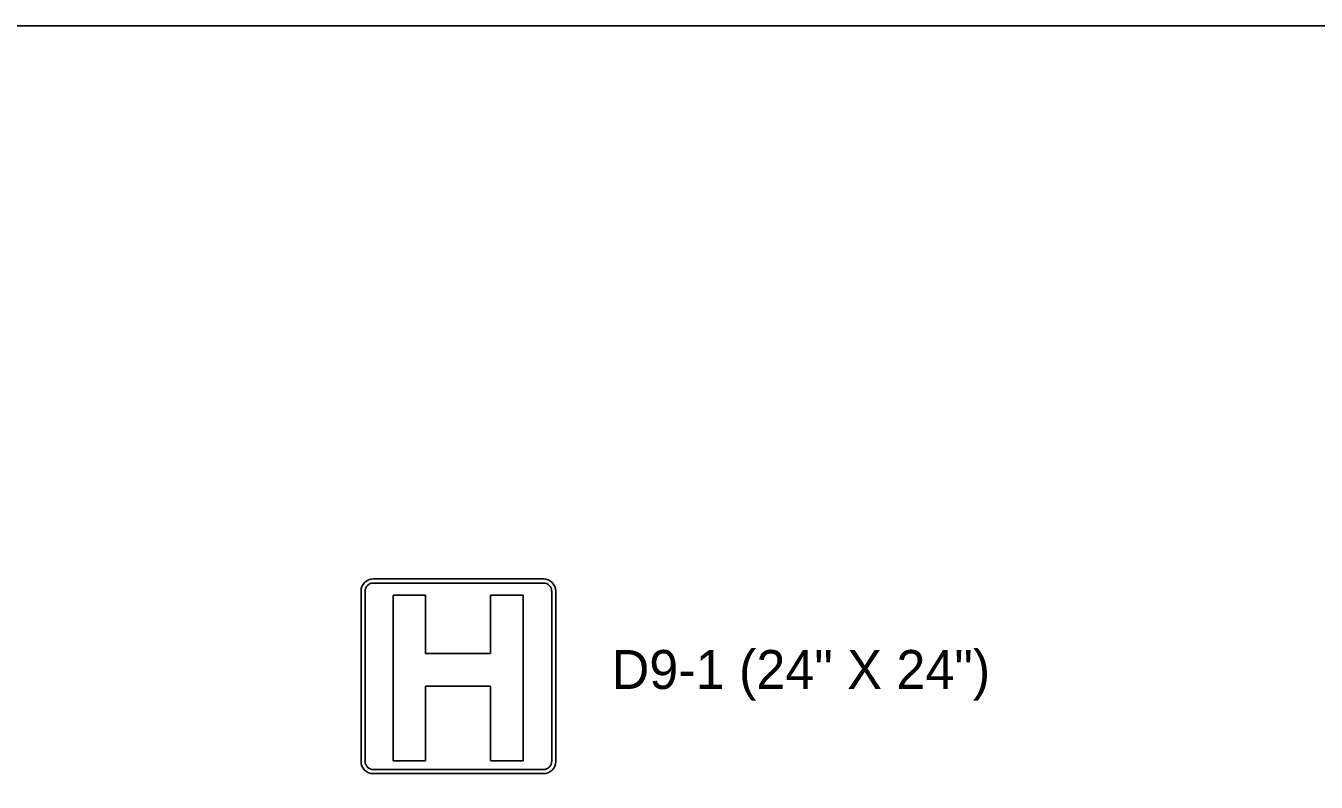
# Model space of a CAD drawing. Extents: x 1001568 to 1002149, y 1840825 to 1841423.
# Drawn here: x 1001937.13 to 1001950.38, y 1841302.89 to 1841310.67 of the extents above; entities that cross this region are included whole.
import ezdxf

# ---------------------------------------------------------------- set-up
doc = ezdxf.new("R2010")
doc.units = 0
for name, color, linetype in [('40', 7, 'Continuous'), ('R_No Plot', 7, 'Continuous'), ('SIGNS', 7, 'Continuous')]:
    doc.layers.add(name, color=color, linetype=linetype)

msp = doc.modelspace()

# ---------------------------------------------------------------- linework, layer by layer
at = {"layer": 'R_No Plot'}
msp.add_lwpolyline([(1001886.411, 1841310.667), (1001964.232, 1841310.667), (1001964.232, 1841307.694), (1001968.454, 1841307.694), (1001968.454, 1841306.882), (1001982.133, 1841306.882), (1001982.133, 1841248.127), (1001886.411, 1841248.127)], close=True, dxfattribs=at)
at = {"layer": 'SIGNS'}
for p, q in [((1001940.696, 1841304.983), (1001942.446, 1841304.983)), ((1001940.696, 1841304.983), (1001942.446, 1841304.983)), ((1001942.446, 1841304.941), (1001940.696, 1841304.941)), ((1001940.571, 1841303.108), (1001940.571, 1841304.858)), ((1001940.571, 1841303.108), (1001940.571, 1841304.858)), ((1001940.613, 1841304.858), (1001940.613, 1841303.108)), ((1001940.902, 1841303.116), (1001940.902, 1841304.816)), ((1001940.902, 1841304.816), (1001941.235, 1841304.816)), ((1001940.902, 1841303.116), (1001940.902, 1841304.816)), ((1001940.902, 1841304.816), (1001941.235, 1841304.816)), ((1001941.235, 1841304.816), (1001941.235, 1841304.216)), ((1001941.235, 1841304.816), (1001941.235, 1841304.216)), ((1001941.902, 1841304.216), (1001941.902, 1841304.816)), ((1001941.902, 1841304.816), (1001942.235, 1841304.816)), ((1001941.902, 1841304.216), (1001941.902, 1841304.816)), ((1001941.902, 1841304.816), (1001942.235, 1841304.816)), ((1001942.235, 1841304.816), (1001942.235, 1841303.116)), ((1001942.235, 1841304.816), (1001942.235, 1841303.116)), ((1001942.53, 1841303.108), (1001942.53, 1841304.858)), ((1001942.571, 1841304.858), (1001942.571, 1841303.108)), ((1001942.571, 1841304.858), (1001942.571, 1841303.108)), ((1001941.235, 1841304.216), (1001941.902, 1841304.216)), ((1001941.235, 1841304.216), (1001941.902, 1841304.216)), ((1001941.902, 1841303.883), (1001941.235, 1841303.883)), ((1001941.235, 1841303.883), (1001941.235, 1841303.116)), ((1001941.902, 1841303.883), (1001941.235, 1841303.883)), ((1001941.235, 1841303.883), (1001941.235, 1841303.116)), ((1001941.902, 1841303.116), (1001941.902, 1841303.883)), ((1001941.902, 1841303.116), (1001941.902, 1841303.883)), ((1001940.696, 1841303.024), (1001942.446, 1841303.024)), ((1001941.235, 1841303.116), (1001940.902, 1841303.116)), ((1001941.235, 1841303.116), (1001940.902, 1841303.116)), ((1001942.235, 1841303.116), (1001941.902, 1841303.116)), ((1001942.235, 1841303.116), (1001941.902, 1841303.116)), ((1001942.446, 1841302.983), (1001940.696, 1841302.983)), ((1001942.446, 1841302.983), (1001940.696, 1841302.983))]:
    msp.add_line(p, q, dxfattribs=at)
for centre, radius, start, end in [((1001940.696, 1841304.858), 0.125, 89.9998, 180), ((1001940.696, 1841304.858), 0.125, 89.9998, 180), ((1001940.696, 1841304.858), 0.0833, 89.9998, 180), ((1001942.446, 1841304.858), 0.125, 0.0002, 89.9998), ((1001942.446, 1841304.858), 0.125, 0.0002, 89.9998), ((1001942.446, 1841304.858), 0.0833, 0.0002, 89.9998), ((1001940.696, 1841303.108), 0.125, 179.9997, 269.9999), ((1001940.696, 1841303.108), 0.125, 179.9997, 269.9999), ((1001940.696, 1841303.108), 0.0833, 179.9997, 269.9999), ((1001942.446, 1841303.108), 0.125, 269.9999, 0.0002), ((1001942.446, 1841303.108), 0.125, 269.9999, 0.0002), ((1001942.446, 1841303.108), 0.0833, 269.9999, 0.0002)]:
    msp.add_arc(centre, radius, start, end, dxfattribs=at)

# ---------------------------------------------------------------- texts
at = {"layer": '40'}
msp.add_text('D9-1 (24" X 24")', height=0.4, rotation=0, dxfattribs=at).set_placement((1001943.146, 1841303.853))

doc.saveas('drawing.dxf')
